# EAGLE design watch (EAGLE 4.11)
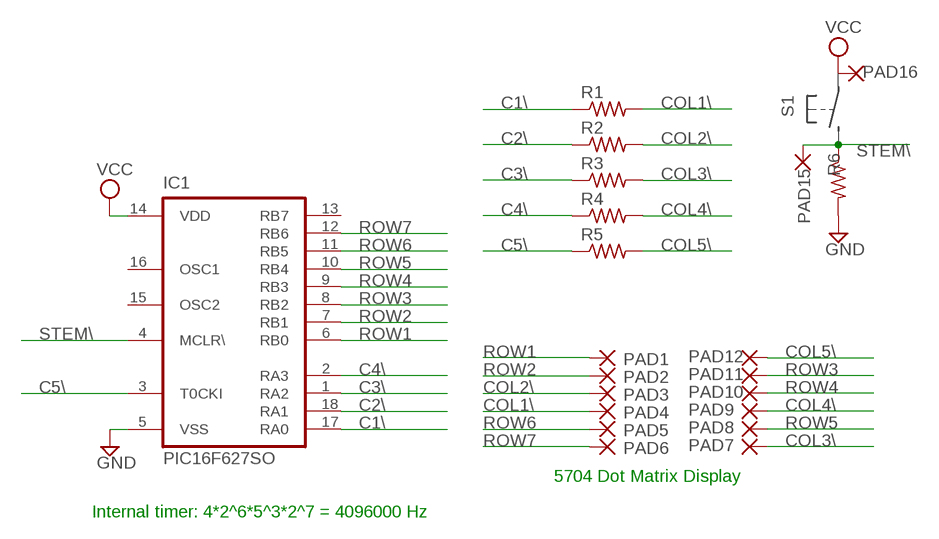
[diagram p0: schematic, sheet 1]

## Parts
IC1  PIC16F627SO  PIC16C622SO  [SO-18W]
PAD1  SMD2  [SMD2]
PAD2  SMD2  [SMD2]
PAD3  SMD2  [SMD2]
PAD4  SMD2  [SMD2]
PAD5  SMD2  [SMD2]
PAD6  SMD2  [SMD2]
PAD7  SMD2  [SMD2]
PAD8  SMD2  [SMD2]
PAD9  SMD2  [SMD2]
PAD10  SMD2  [SMD2]
PAD11  SMD2  [SMD2]
PAD12  SMD2  [SMD2]
PAD15  SMD2  [SMD2]
PAD16  SMD2  [SMD2]
R1  R-US_R0805  [R0805]
R2  R-US_R0805  [R0805]
R3  R-US_R0805  [R0805]
R4  R-US_R0805  [R0805]
R5  R-US_R0805  [R0805]
R6  R-US_R0805  [R0805]

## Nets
C1\: IC1.17(RA0) R1.1
C2\: IC1.18(RA1) R2.1
C3\: IC1.1(RA2) R3.1
C4\: IC1.2(RA3) R4.1
C5\: IC1.3(T0CKI) R5.1
COL1\: PAD4.1(P) R1.2
COL2\: PAD3.1(P) R2.2
COL3\: PAD7.1(P) R3.2
COL4\: PAD9.1(P) R4.2
COL5\: PAD12.1(P) R5.2
GND: IC1.5(VSS) R6.2
ROW1: IC1.6(RB0) PAD1.1(P)
ROW2: IC1.7(RB1) PAD2.1(P)
ROW3: IC1.8(RB2) PAD11.1(P)
ROW4: IC1.9(RB3) PAD10.1(P)
ROW5: IC1.10(RB4) PAD8.1(P)
ROW6: IC1.11(RB5) PAD5.1(P)
ROW7: IC1.12(RB6) PAD6.1(P)
STEM\: IC1.4(MCLR\) PAD15.1(P) R6.1
VCC: IC1.14(VDD) PAD16.1(P)
Unconnected: IC1.13(RB7) IC1.15(OSC2) IC1.16(OSC1)

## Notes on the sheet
- 5704 Dot Matrix Display
- Internal timer: 4*2^6*5^3*2^7 = 4096000 Hz

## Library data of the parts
IC1 = microchip:PIC16C*: MICROCONTROLLER PIC16C5X family: EPROM/ROM-based PIC16C55X family: EPROM-based PIC16C6X family PIC16CE62X family: analog comparators/EEPROM data memory PIC16C7X family: A/D converter PIC16C71X family: A/D converter PIC16F8X family: flash EEPROM Pin compatible devices: PIC16C154, PIC16CR154,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
PAD1-PAD12 PAD15 PAD16 = wirepad:SMD2: SMD PAD
R1-R6 = rcl:R-US_: RESISTOR, American symbol

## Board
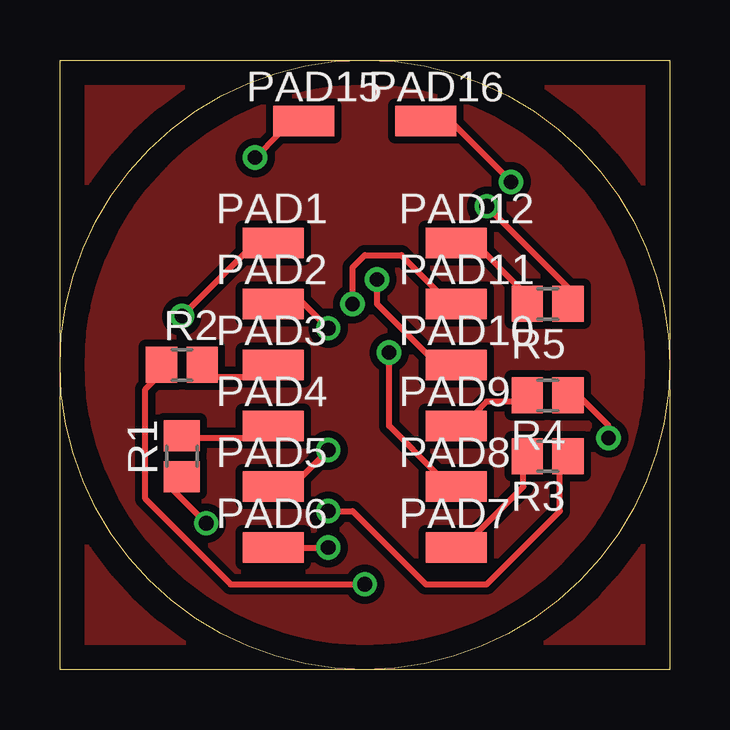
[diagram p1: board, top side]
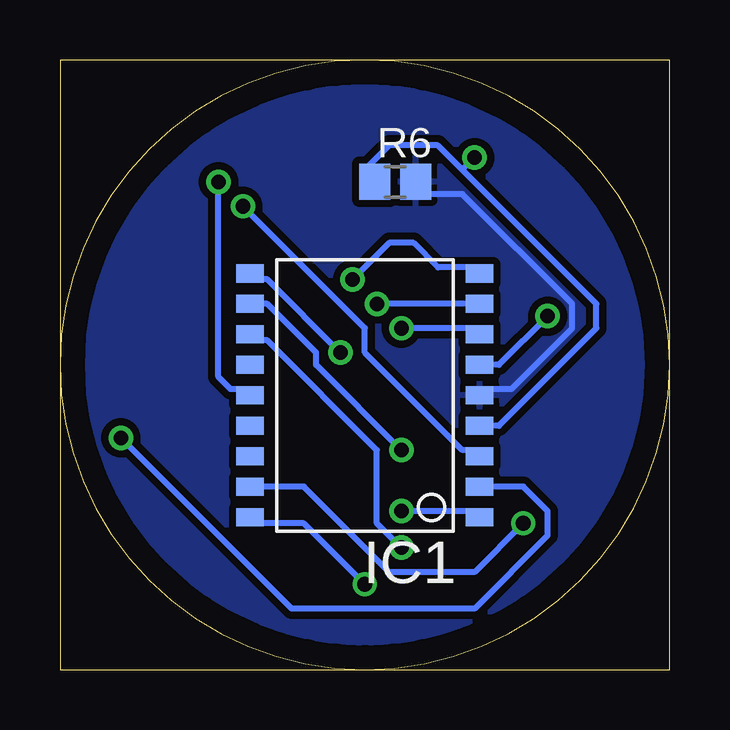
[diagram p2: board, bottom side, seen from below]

Size 25.4 x 25.4 mm. Coordinates in mm from the lower left corner, seen from the top.
Outline: 0,12.7 0,0 25.4,0 25.4,12.7
Outline: 0,12.7 0,25.4 24.13,25.4 25.4,25.4 25.4,12.7
Outline: 0,12.7 arc-180 25.4,12.7
Outline: 25.4,12.7 arc-180 0,12.7
Copper layers (1*16): Top 0.035mm / dielectric 1.5mm / Bottom 0.035mm
Design rules "custompcb": minimum track width 10mil, minimum drill 24mil, track to track 12mil, track to pad 12mil, pad to pad 12mil, via to via 12mil, smd to smd 12mil, copper to edge 40mil, drill to drill 12mil, minimum pad ring 10mil, minimum via ring 8mil, stop-mask expansion 0mil, vias tented up to drill 0mil, thermal gap 10mil

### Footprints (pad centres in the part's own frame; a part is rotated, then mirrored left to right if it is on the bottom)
SO-18W = smd 0.762 x 1.143: 1 -5.08,-4.788; 2 -3.81,-4.788; 3 -2.54,-4.788; 4 -1.27,-4.788; 5 0,-4.788; 6 1.27,-4.788; 7 2.54,-4.788; 8 3.81,-4.788; 9 5.08,-4.788; 10 5.08,4.788; 11 3.81,4.788; 12 2.54,4.788; 13 1.27,4.788; 14 0,4.788; 15 -1.27,4.788; 16 -2.54,4.788; 17 -3.81,4.788; 18 -5.08,4.788
SMD2 = smd 1.27 x 2.54: 1 0,0
R0805 = smd 1.3 x 1.5: 1 -0.85,0; 2 0.85,0

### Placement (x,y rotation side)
IC1  12.7,11.43 90 bottom
PAD1  8.89,17.78 270 top
PAD2  8.89,15.24 270 top
PAD3  8.89,12.7 270 top
PAD4  8.89,10.16 270 top
PAD5  8.89,7.62 270 top
PAD6  8.89,5.08 270 top
PAD7  16.51,5.08 270 top
PAD8  16.51,7.62 270 top
PAD9  16.51,10.16 270 top
PAD10  16.51,12.7 270 top
PAD11  16.51,15.24 270 top
PAD12  16.51,17.78 270 top
PAD15  10.16,22.86 270 top
PAD16  15.24,22.86 270 top
R1  5.08,8.89 90 top
R2  5.08,12.7 0 top
R3  20.32,8.89 180 top
R4  20.32,11.43 180 top
R5  20.32,15.24 180 top
R6  11.43,20.32 0 bottom

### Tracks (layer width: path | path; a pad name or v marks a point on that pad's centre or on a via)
C1\  (via drill 0.61)
  Top 0.254: v6.1,6.1 4.57,7.62 R1.1
  Bottom 0.254: v6.1,6.1 8.13,4.06 11.68,4.06 15.24,7.62 17.27,7.62 IC1.17
C2\  (via drill 0.61)
  Top 0.254: v12.7,3.56 7.11,3.56 3.56,7.11 3.56,11.68 4.06,12.19 R2.1
  Bottom 0.254: v12.7,3.56 15.24,6.1 17.27,6.1 IC1.18
C3\  (via drill 0.61)
  Top 0.254: v11.18,6.6 12.19,6.6 15.24,3.56 17.78,3.56 20.83,6.6 20.83,8.64 R3.1
  Bottom 0.254: v11.18,6.6 8.13,6.6 IC1.1
C4\  (via drill 0.61)
  Top 0.254: v22.86,9.65 22.86,10.16 21.34,11.68 R4.1
  Bottom 0.254: v22.86,9.65 15.75,2.54 8.13,2.54 5.08,5.59 5.08,6.6 6.1,7.62 7.62,7.62 IC1.2
C5\  (via drill 0.61)
  Top 0.254: v17.78,19.3 21.34,15.75 R5.1
  Bottom 0.254: v17.78,19.3 12.7,14.22 12.7,13.21 8.64,9.14 8.13,9.14 IC1.3
COL1\
  Top 0.254: R1.2 5.59,9.65 8.13,9.65 PAD4.1
COL2\
  Top 0.254: R2.2 6.1,12.19 8.13,12.19 PAD3.1
COL3\
  Top 0.254: R3.2 19.3,8.64 19.3,7.62 17.27,5.59 PAD7.1
COL4\
  Top 0.254: R4.2 19.3,11.18 17.78,11.18 17.27,10.67 PAD9.1
COL5\
  Top 0.254: R5.2 19.3,15.75 17.27,17.78 PAD12.1
GND
  Bottom 0.254: IC1.5 7.62,11.68 6.6,11.68 4.06,14.22 4.06,15.24 8.64,19.81 10.16,19.81 R6.2
  pour Top: 0,0 25.4,0 25.4,25.4 0,25.4
  pour Bottom: 0,0 25.4,0 25.4,25.4 0,25.4
ROW1  (via drill 0.61)
  Top 0.254: v5.08,14.73 8.13,17.78 PAD1.1
  Bottom 0.254: v5.08,14.73 7.11,12.7 7.62,12.7 IC1.6
ROW2  (via drill 0.61)
  Top 0.254: v11.18,14.22 9.65,15.75 PAD2.1
  Bottom 0.254: v11.18,14.22 8.13,14.22 IC1.7
ROW3  (via drill 0.61)
  Top 0.254: v12.19,15.24 12.19,16.76 12.7,17.27 14.22,17.27 15.75,15.75 PAD11.1
  Bottom 0.254: v12.19,15.24 8.13,15.24 IC1.8
ROW4  (via drill 0.61)
  Top 0.254: v13.21,16.26 13.21,15.24 15.75,12.7 PAD10.1
  Bottom 0.254: v13.21,16.26 11.68,17.78 10.67,17.78 9.65,16.76 8.13,16.76 IC1.9
ROW5  (via drill 0.61)
  Top 0.254: v13.72,13.21 13.72,10.16 15.75,8.13 PAD8.1
  Bottom 0.254: v13.72,13.21 16.76,16.26 17.27,16.26 IC1.10
ROW6  (via drill 0.61)
  Top 0.254: v11.18,9.14 9.65,7.62 PAD5.1
  Bottom 0.254: v11.18,9.14 14.73,12.7 14.73,13.21 16.76,15.24 17.27,15.24 IC1.11
ROW7  (via drill 0.61)
  Top 0.254: v11.18,5.08 9.65,5.08 PAD6.1
  Bottom 0.254: v11.18,5.08 12.19,6.1 12.19,9.14 16.76,13.72 17.27,13.72 IC1.12
STEM\  (via drill 0.61)
  Top 0.254: v8.13,21.34 9.14,22.35 PAD15.1
  Bottom 0.254: 8.64,20.83 9.65,21.84 11.68,21.84 12.7,20.83 R6.1 | 8.64,20.83 3.05,15.24 3.05,14.22 7.11,10.16 7.62,10.16 IC1.4 | 8.64,20.83 v8.13,21.34
VCC  (via drill 0.61)
  Top 0.254: v18.8,20.32 16.26,22.86 PAD16.1
  Bottom 0.254: v18.8,20.32 18.8,12.19 18.29,11.68 17.78,11.68 IC1.14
